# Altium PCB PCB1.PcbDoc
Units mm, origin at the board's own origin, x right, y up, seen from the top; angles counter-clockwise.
Board outline 46.48 x 19.05 mm, 2 copper layers (Top Layer, Bottom Layer); 17 components, 19 nets, 92 pads, 16 vias.
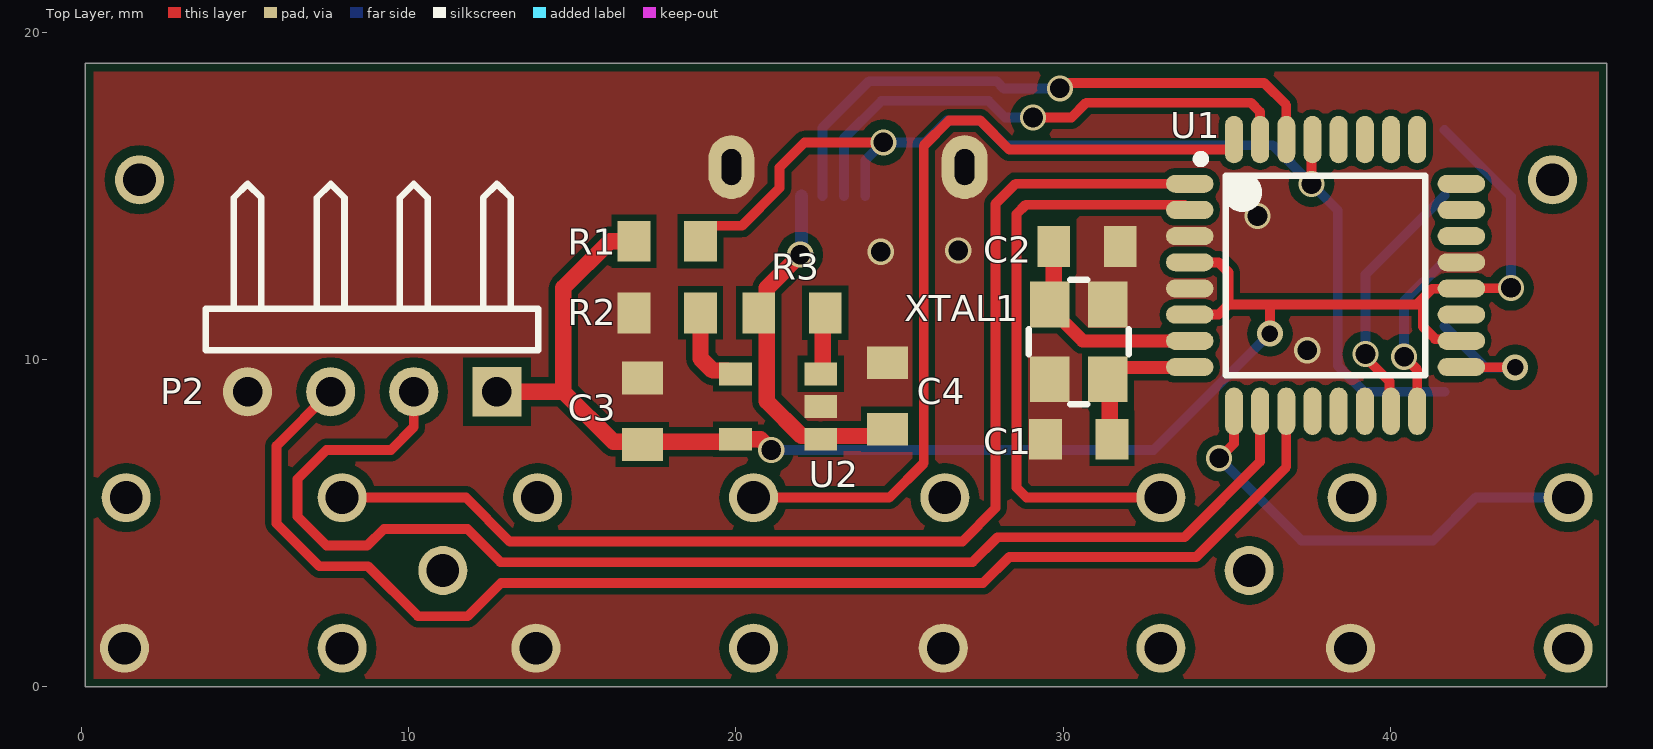
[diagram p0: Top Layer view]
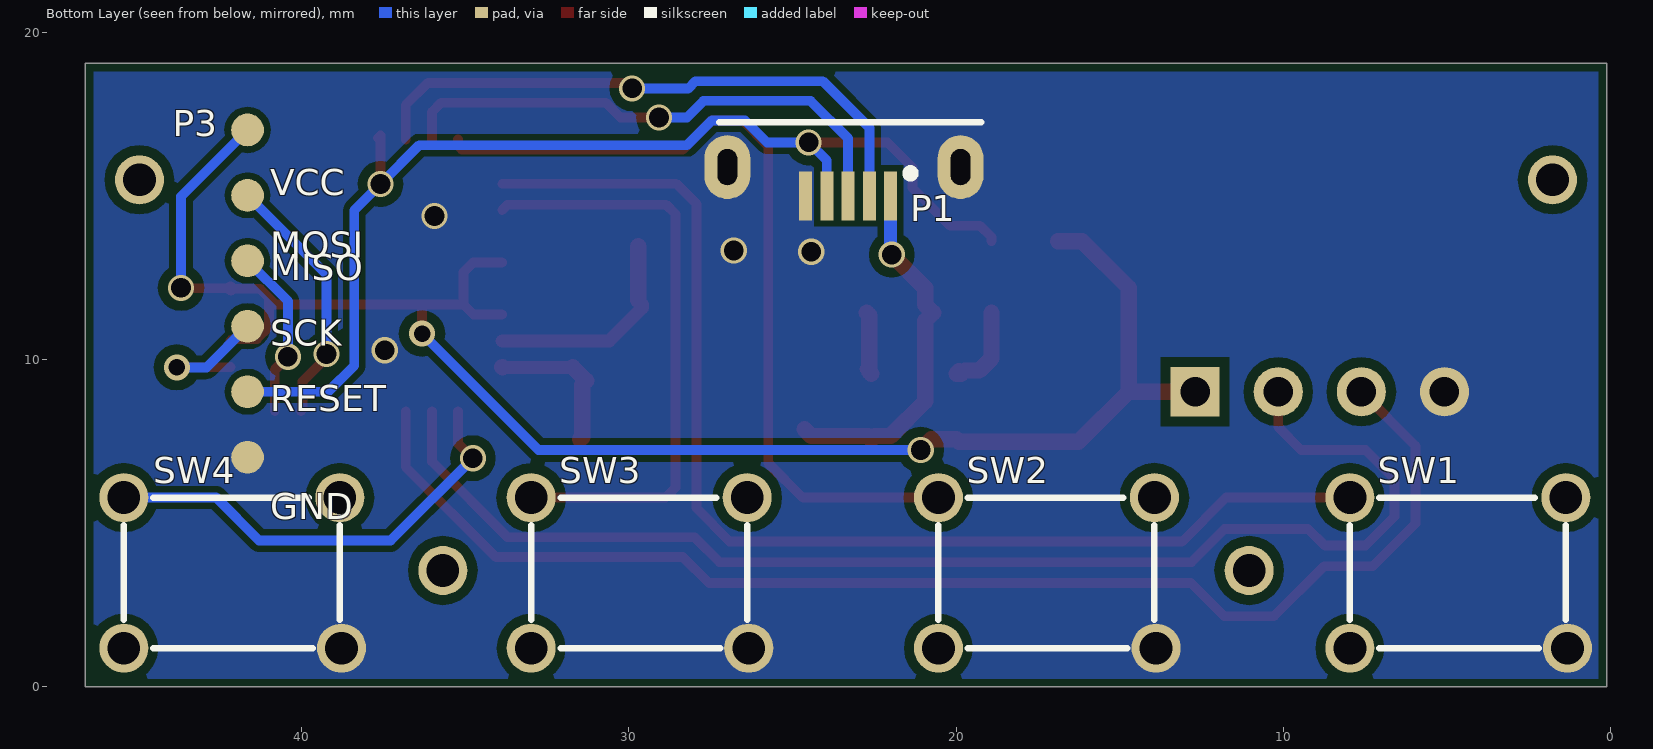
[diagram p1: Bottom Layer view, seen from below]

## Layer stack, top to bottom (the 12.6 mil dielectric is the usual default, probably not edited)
Top Solder: solder mask 0.0102, Solder Resist, Dk 3.5
Top Layer: signal copper 0.0356
Dielectric 1: dielectric 0.32, FR-4, Dk 4.8
Bottom Layer: signal copper 0.0356
Bottom Solder: solder mask 0.0102, Solder Resist, Dk 3.5

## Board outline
0.127,0 46.609,0 46.609,19.05 0.127,19.05

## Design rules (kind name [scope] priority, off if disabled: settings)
Clearance [All] p1: gap=0.3 ignorepadtopadclearanceinfootprint=FALSE except(0.2: Arc-SMDPad Arc-Fill Arc-Poly Arc-Region Track-SMDPad Track-Fill Track-Poly Track-Region SMDPad-SMDPad SMDPad-Fill SMDPad-Poly SMDPad-Region)
PolygonConnect [All] p1: connectstyle=Direct reliefconductorwidth=0.254 reliefentries=4 polygonreliefangle="90 Angle" airgapwidth=0.254
RoutingVias [All] p1: holewidth=0.5 width=0.8 viastyle="Through Hole" minholewidth=0.2 minwidth=0.5 maxholewidth=0.5 maxwidth=1
SolderMaskExpansion [All] p1: expansion=0.102
UnRoutedNet [All] p1: checkbadconnections=TRUE
Width [All] p1: maxlimit=0.5 minlimit=0.254 preferedwidth=0.4 minimp=50.000000 maximp=50.000000 favimp=50.000000
29 further rules are at their usual default settings.

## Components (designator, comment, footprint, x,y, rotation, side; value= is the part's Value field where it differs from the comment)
C1 "22pF" CAP0805 30.48,7.565 r0 top
C2 "22pF" CAP0805 30.734,13.462 r180 top
C3 "0.1uF" CAP0805 17.145,8.423 r270 top
C4 "10uF" CAP0805 24.638,8.89 r270 top
P1 "Mikro USB" "USB TYPE B" 23.368,16.383 r0 bottom locked
P2 "LED Strip Conn." HDR1X4H 12.7,9.017 r180 top
P3 "ICSP Conn." "ICSP Conn." 41.656,12.018 r270 bottom locked
R1 "10k" RES0805 17.907,13.616 r0 top
R2 "309Ω" RES0805 17.907,11.43 r0 top
R3 "0" RES0805 21.717,11.43 r0 top
SW1 "Button" BUTTON 4.445,3.683 r180 bottom locked
SW2 "Button" BUTTON 17.018,3.683 r180 bottom locked
SW3 "Button" BUTTON 29.464,3.683 r180 bottom locked
SW4 "Button" BUTTON 41.91,3.683 r180 bottom locked
U1 "ATmega328P-AU" Atmega328P-AU 37.973,12.573 r0 top
U2 "FPF2124" SOT23-5 19.493,9.965 r180 top
XTAL1 "16MHz" "Crystal 3.2x2.5" 32.004,12.446 r90 top

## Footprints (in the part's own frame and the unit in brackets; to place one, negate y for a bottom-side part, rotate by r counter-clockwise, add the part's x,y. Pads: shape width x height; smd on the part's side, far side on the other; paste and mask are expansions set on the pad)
Atmega328P-AU [mm]
  oval 1.45x0.55 smd: 1(-4.1,2.8) 2(-4.1,2) 3(-4.1,1.2) 4(-4.1,0.4) 5(-4.1,-0.4) 6(-4.1,-1.2) 7(-4.1,-2) 8(-4.1,-2.8) 17(4.2,-2.8) 18(4.2,-2) 19(4.2,-1.2) 20(4.2,-0.4) 21(4.2,0.4) 22(4.2,1.2) 23(4.2,2) 24(4.2,2.8)
  oval 0.55x1.45 smd: 9(-2.75,-4.15) 10(-1.95,-4.15) 11(-1.15,-4.15) 12(-0.35,-4.15) 13(0.45,-4.15) 14(1.25,-4.15) 15(2.05,-4.15) 16(2.85,-4.15) 25(2.85,4.15) 26(2.05,4.15) 27(1.25,4.15) 28(0.45,4.15) 29(-0.35,4.15) 30(-1.15,4.15) 31(-1.95,4.15) 32(-2.75,4.15)
  silkscreen extent -3.88,-3.05 3.1,3.68, body extent -4.45,-4.5 4.55,4.5, height 1.45
BUTTON [mm]
  round 1.5 hole 1: 1(-3.525,2.1) 2(3.075,2.1) 3(-3.525,-2.5) 4(3.125,-2.5)
  silkscreen extent -3.53,-2.5 3.07,2.1
CAP0805 [mm]
  rect 1x1.25 smd: 1(-1.016,0) 2(1.016,0)
  body extent -1.1,-0.72 1.11,0.72, height 0.94
"Crystal 3.2x2.5" [mm]
  rect 1.4x1.2 smd: 1(-3.048,0.635) 2(-0.762,0.635) 3(-0.762,2.413) 4(-3.048,2.413)
  silkscreen extent -3.81,0 0,3.05, body extent -3.5,0.27 -0.31,2.77, height 1.35
HDR1X4H [mm] "Connector; Header; 4 Position; Right Angle"
  rect 1.5x1.5 hole 0.9: 1(0,0)
  round 1.5 hole 0.9: 2(2.54,0) 3(5.08,0) 4(7.62,0)
  silkscreen extent -1.27,-6.35 8.89,-1.27
"ICSP Conn." [mm]
  round 1 smd: 1(-5,0) 2(-3,0) 3(-1,0) 4(1,0) 5(3,0) 6(5,0)
RES0805 [mm]
  rect 1x1.25 smd: 1(-1.016,0) 2(1.016,0)
  body extent -1.1,-0.72 1.11,0.72, height 0.94
SOT23-5 [mm]
  rect 1x0.7 smd: 1(-3.1,2.4) 2(-3.1,1.4) 3(-3.1,0.4) 4(-0.5,0.4) 5(-0.5,2.4)
"USB TYPE B" [mm]
  rect 0.4x1.5 smd: 1(-1.364,1.381) 2(-0.714,1.381) 3(-0.064,1.381) 4(0.586,1.381) 5(1.236,1.381)
  oval 1.4x1.95 hole 1.1 slot 0.6 at 0 deg: 5(-3.5,0.5) 6(3.625,0.5)
  silkscreen extent -4.13,-0.87 3.87,0.82

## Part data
C1 C2 C3 C4: library part Cap, "0603"
P2: library part "Header 4H", "Header, 4-Pin, Right Angle"
R1 R2 R3: library part Resistor, "0603"
U1: library part MC-8B-ATM48-SQ32, "8-bit AVR Microcontroller, 32KB Flash, 1KB EEPROM, 2KB SRAM, 32-pin TQFP, Industrial Grade (-40°C to 85°C)"
XTAL1: library part Crystal4Pin

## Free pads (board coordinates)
  round 1.5 hole 1: 2(11.049,3.556) 3(35.687,3.556) 4(1.778,15.494) 5(44.958,15.494)

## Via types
v1: diameter 0.8, hole 0.6, Top Layer to Bottom Layer, tented both sides, 11 vias
v2: diameter 0.8, hole 0.6, Top Layer to Bottom Layer, 3 vias
v3: diameter 0.8, hole 0.5, Top Layer to Bottom Layer, 1 vias
v4: diameter 0.8, hole 0.5, Top Layer to Bottom Layer, tented both sides, 1 vias

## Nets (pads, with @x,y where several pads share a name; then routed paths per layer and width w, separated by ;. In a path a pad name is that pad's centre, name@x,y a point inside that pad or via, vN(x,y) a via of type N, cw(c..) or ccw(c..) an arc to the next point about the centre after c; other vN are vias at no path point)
+5V: C3.2 P2.1 P3.1 R1.1 U1.4 U1.6 U1.18 U1.20 U2.5 | length 53.1
  Top Layer w0.3: U1.6 33.883,11.383 34.751,11.383 35.052,11.684 ; U1.4 33.883,12.963 34.759,12.963 35.052,12.671 35.052,11.684 ; v4(36.322,10.795) 36.322,11.684 ; U1.20@42.163,12.163 41.278,12.163 40.998,11.883 ; U1.18 42.125,10.621 41.363,10.621 41.363,10.639 40.998,11.004 40.998,11.883 ; U1.20@42.183,12.183 v2@43.679,12.183 ; 35.052,11.684 36.322,11.684 ; 36.322,11.684 40.799,11.684 40.998,11.883
  Top Layer w0.4: U1.20@42.163,12.163 U1.20 U1.20@42.183,12.183 ; v2@43.679,12.183 v2(43.688,12.192)
  Top Layer w0.5: P2.1 14.732,9.017 ; R1.1 16.156,13.616 14.732,12.192 14.732,9.017 ; v1(21.082,7.239) 20.756,7.565 U2.5 19.914,7.486 16.263,7.486 14.732,9.017
  Bottom Layer w0.3: v1(21.082,7.239) 32.766,7.239 v4(36.322,10.795) ; P3.1 43.688,14.986 v2(43.688,12.192)
GND: C1.1 C2.1 C3.1 C4.1 P1.5 P1.6 P2.4 P3.6 R2.1 SW1.4 SW2.4 SW3.4 SW4.4 U1.3 U1.5 U1.21 U2.2 XTAL1.2 XTAL1.4
  other v1: 37.465,10.287 24.429,13.293 26.797,13.335 35.941,14.388
MISO: P3.3 U1.16 | length 5.3
  Top Layer w0.3: v2(40.423,10.089) 40.823,9.689 U1.16
  Bottom Layer w0.3: v2(40.423,10.089) 40.423,11.785 P3.3
MOSI: P3.2 U1.15 | length 7.9
  Top Layer w0.3: v2(39.243,10.172) 39.243,10.067 39.975,9.335 39.975,8.471 U1.15
  Bottom Layer w0.3: v2(39.243,10.172) 39.243,12.605 P3.2
NetC1_2: C1.2 U1.8 XTAL1.1 | length 4.6
  Top Layer w0.4: XTAL1.1@31.719,9.763 U1.8@33.863,9.763
  Top Layer w0.5: C1.2 31.432,7.628 31.432,9.223 31.305,9.35 XTAL1.1@31.719,9.763 ; U1.8@33.863,9.763 U1.8
NetC2_2: C2.2 U1.7 XTAL1.3 | length 6.6
  Top Layer w0.4: XTAL1.3@29.718,11.811 XTAL1.3 29.591,11.584 30.602,10.573 U1.7
  Top Layer w0.5: XTAL1.3@29.718,11.811 C2.2
NetP2_2: P2.2 U1.10 | length 39.7
  Top Layer w0.3: P2.2 10.16,7.938 9.461,7.239 7.493,7.239 6.604,6.35 6.604,5.207 7.493,4.318 8.739,4.318 9.247,4.826 11.798,4.826 12.814,3.81 27.237,3.81 27.999,4.572 33.714,4.572 36.023,6.881 U1.10
NetP2_3: P2.3 U1.11 | length 40.3
  Top Layer w0.3: P2.3 5.969,7.366 5.969,4.993 7.279,3.683 8.77,3.683 10.294,2.159 11.811,2.159 12.827,3.175 27.559,3.175 28.356,3.972 34.071,3.972 36.823,6.724 U1.11
NetR2_2: R2.2 U2.4 | length 2.8
  Top Layer w0.5: R2.2 18.923,10.033 19.291,9.665 19.743,9.665 19.843,9.565 U2.4 U2.4@19.913,9.645
NetR3_2: R3.2 U2.3 | length 2.1
  Top Layer w0.4: U2.3 22.602,9.565 U2.3@22.752,9.715
  Top Layer w0.5: U2.3 22.663,9.635 22.663,11.36 R3.2
NetSW1_1: SW1.1 U1.1 | length 36.4
  Top Layer w0.3: SW1.1 11.752,5.783 13.09,4.445 26.924,4.445 27.941,5.462 27.941,14.761 28.553,15.373 U1.1
NetSW2_1: SW2.1 U1.32 | length 25.7
  Top Layer w0.3: SW2.1 24.692,5.783 25.743,6.834 25.743,16.534 26.517,17.308 27.469,17.308 28.354,16.423 35.108,16.423 35.223,16.538 U1.32
NetSW3_1: SW3.1 U1.2 | length 18.4
  Top Layer w0.3: SW3.1 28.888,5.783 28.575,6.096 28.575,14.446 28.861,14.732 33.714,14.732 U1.2
NetSW4_1: SW4.1 U1.9 | length 13.9
  Top Layer w0.3: v1(34.77,6.985) 35.223,7.438 U1.9
  Bottom Layer w0.3: v1(34.77,6.985) 37.282,4.473 41.303,4.473 42.613,5.783 SW4.1
PD0: P1.2 U1.30 | length 18.3
  Top Layer w0.3: v1(29.904,18.288) 30.064,18.448 36.149,18.448 36.823,17.774 U1.30
  Bottom Layer w0.3: P1.2 22.654,17.085 24.077,18.508 27.966,18.508 28.186,18.288 v1(29.904,18.288)
PD1: P1.3 U1.31 | length 16.3
  Top Layer w0.3: v1(29.083,17.399) 30.259,17.399 30.708,17.848 35.746,17.848 36.023,17.571 U1.31
  Bottom Layer w0.3: P1.3 23.304,16.765 24.447,17.908 27.718,17.908 28.227,17.399 v1(29.083,17.399)
RES: P1.4 P3.5 R1.2 U1.29 | length 34.4
  Top Layer w0.3: R1.2 18.923,13.741 19.273,14.091 20.187,14.091 21.336,15.24 21.336,15.875 22.098,16.637 v1(24.511,16.637) ; v1(37.592,15.367) 37.592,16.85 37.671,16.771 U1.29
  Bottom Layer w0.3: P1.4 23.954,16.08 v1(24.511,16.637) 25.781,16.637 26.452,17.308 27.469,17.308 28.228,16.549 36.41,16.549 v1(37.592,15.367) 38.393,14.566 38.393,9.82 39.195,9.018 P3.5
SCK: P3.4 U1.17 | length 4.3
  Top Layer w0.3: U1.17 42.178,9.768 43.81,9.768 v3(43.815,9.763)
  Bottom Layer w0.3: P3.4 42.911,9.763 v3(43.815,9.763)
VIN: C4.2 P1.1 R3.1 U2.1 | length 11.2
  Top Layer w0.5: v1(21.971,13.208) 20.951,12.188 20.951,11.68 R3.1 20.943,11.188 20.943,8.729 22.007,7.665 22.493,7.665 U2.1 22.693,7.665 24.429,7.665 C4.2
  Bottom Layer w0.4: v1(21.971,13.208) 22.004,13.241 P1.1
pads on no net: SW1.2 SW1.3 SW2.2 SW2.3 SW3.2 SW3.3 SW4.2 SW4.3 U1.12 U1.13 U1.14 U1.19 U1.22 U1.23 U1.24 U1.25 U1.26 U1.27 U1.28

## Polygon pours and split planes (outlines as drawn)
GND on Top Layer "Top Layer-GND" (solid, pour order 0): 0.381,18.796 46.376,18.796 46.376,0.249 0.381,0.249 0.381,18.796 0.635,18.796
GND on Bottom Layer "Top Layer-GND" (solid, pour order 2): 0.381,18.796 46.355,18.796 46.355,0.254 0.381,0.254

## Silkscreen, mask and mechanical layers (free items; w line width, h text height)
Mechanical 13:
  the board outline again, w0.2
